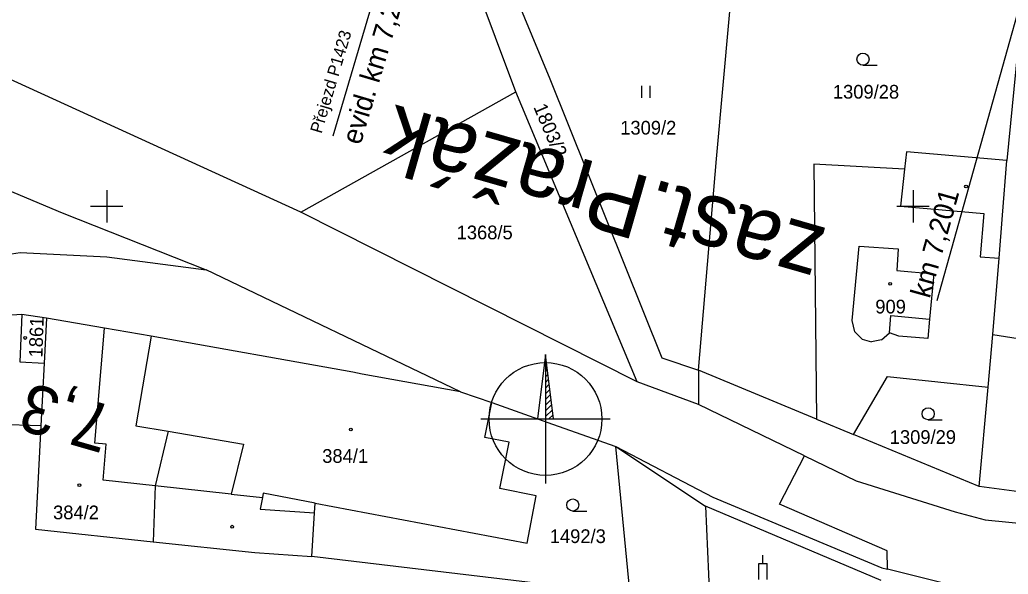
# Model space of a CAD drawing. Extents: x -779302 to -774398, y -1144902 to -1142831.
# Drawn here: x -777410.8 to -777288.2, y -1143845.6 to -1143776.9 of the extents above; entities that cross this region are included whole.
import ezdxf

# ---------------------------------------------------------------- set-up
doc = ezdxf.new("R2010")
doc.units = 0
for name, color, linetype in [('hektosit - Vrstva 5', 7, 'Continuous'), ('Hranice parcel', 7, 'Continuous'), ('Parcelní čísla', 7, 'Continuous'), ('Poz předměty', 7, 'Continuous'), ('Vnitřní kresba', 7, 'Continuous'), ('zjednodus_g_situ-seda - Vrstva 23', 7, 'Continuous'), ('zjednodus_g_situ-seda - Vrstva 4', 7, 'Continuous'), ('zjednodus_g_situ-seda - Vrstva 50', 7, 'Continuous'), ('zjednodus_g_situ-seda - Vrstva 7', 7, 'Continuous'), ('Značky budov', 7, 'Continuous'), ('Značky kultur', 7, 'Continuous')]:
    doc.layers.add(name, color=color, linetype=linetype)

msp = doc.modelspace()

# ---------------------------------------------------------------- linework, layer by layer
at = {"layer": 'hektosit - Vrstva 5'}
for p, q in [((-777400, -1143798), (-777400, -1143802)), ((-777300, -1143798), (-777300, -1143802)), ((-777402, -1143800), (-777398, -1143800)), ((-777302, -1143800), (-777298, -1143800))]:
    msp.add_line(p, q, dxfattribs=at)
at = {"layer": 'Hranice parcel'}
for p, q in [((-777286.39, -1143773.98), (-777288.38, -1143794.34)), ((-777375.94, -1143800.75), (-777349.24, -1143785.82)), ((-777334.23, -1143821.79), (-777349.24, -1143785.82)), ((-777334.23, -1143821.79), (-777375.94, -1143800.75)), ((-777356.13, -1143823.03), (-777387.68, -1143807.89)), ((-777407.46, -1143813.89), (-777410.51, -1143813.42)), ((-777407.46, -1143813.89), (-777407.75, -1143819.47)), ((-777290.68, -1143822.46), (-777290.09, -1143815.91)), ((-777290.09, -1143815.91), (-777270.07, -1143819.08)), ((-777407.75, -1143819.47), (-777408.15, -1143827.26)), ((-777311.97, -1143826.4), (-777326.6, -1143820.32)), ((-777326.6, -1143820.32), (-777326.59, -1143824.61)), ((-777326.59, -1143824.61), (-777334.23, -1143821.79)), ((-777356.13, -1143823.03), (-777352.24, -1143824.36)), ((-777291.81, -1143834.78), (-777290.68, -1143822.46)), ((-777313.47, -1143830.96), (-777326.59, -1143824.61)), ((-777408.15, -1143827.26), (-777418.55, -1143826.88)), ((-777311.97, -1143826.4), (-777307.37, -1143828.31)), ((-777291.81, -1143834.78), (-777307.37, -1143828.31)), ((-777336.84, -1143829.8), (-777325.74, -1143837.19)), ((-777335.13, -1143847.76), (-777336.84, -1143829.8)), ((-777316.56, -1143836.95), (-777313.47, -1143830.96)), ((-777286.82, -1143835.42), (-777291.81, -1143834.78)), ((-777303.21, -1143842.75), (-777316.56, -1143836.95)), ((-777303.94, -1143846.43), (-777325.74, -1143837.19)), ((-777325.74, -1143837.19), (-777324.77, -1143858.48)), ((-777303.16, -1143845.03), (-777303.21, -1143842.75))]:
    msp.add_line(p, q, dxfattribs=at)
for points in [[(-777375.94, -1143800.75), (-777415.86, -1143782.49), (-777462.27, -1143762.62), (-777556.08, -1143726.43)], [(-777349.24, -1143785.82), (-777354.31, -1143772.3), (-777358.14, -1143760.61)], [(-777354.56, -1143760.13), (-777350.41, -1143771.21), (-777345.05, -1143784.18), (-777331.15, -1143818.8), (-777326.6, -1143820.32)], [(-777326.6, -1143820.32), (-777324.39, -1143794.13), (-777321.99, -1143767.59)], [(-777437.2, -1143787.51), (-777405.54, -1143800.83), (-777387.68, -1143807.89)], [(-777288.38, -1143794.34), (-777300.82, -1143793.24), (-777301.05, -1143795.41), (-777312.29, -1143794.79), (-777311.97, -1143826.4)], [(-777290.09, -1143815.91), (-777289.33, -1143806.45), (-777288.91, -1143801.12), (-777288.38, -1143794.34)], [(-777465.49, -1143832.81), (-777457.92, -1143830.94), (-777435.72, -1143811.54), (-777423.12, -1143807.62), (-777410.71, -1143805.75), (-777400, -1143806.27), (-777387.68, -1143807.89)], [(-777410.51, -1143813.42), (-777414.33, -1143813.66), (-777426.36, -1143819.29), (-777430, -1143821.16)], [(-777410.51, -1143813.42), (-777410.76, -1143819.32), (-777407.75, -1143819.47)], [(-777394.47, -1143816.13), (-777400.29, -1143815.13), (-777407.46, -1143813.89)], [(-777394.47, -1143816.13), (-777396.39, -1143827.22), (-777392.36, -1143827.92), (-777394, -1143834.68), (-777394.22, -1143841.61)], [(-777356.13, -1143823.03), (-777368.31, -1143820.81), (-777369.47, -1143820.6), (-777394.47, -1143816.13)], [(-777307.37, -1143828.31), (-777303.15, -1143821.13), (-777290.68, -1143822.46)], [(-777374.57, -1143843.43), (-777374.21, -1143838.03), (-777374.13, -1143836.83), (-777347.87, -1143841.8), (-777346.72, -1143835.94), (-777351.23, -1143835), (-777350.1, -1143829.26), (-777353.11, -1143828.68), (-777352.24, -1143824.36)], [(-777352.24, -1143824.36), (-777344.73, -1143827.04), (-777336.84, -1143829.8)], [(-777408.15, -1143827.26), (-777408.81, -1143840.04), (-777394.22, -1143841.61)], [(-777336.84, -1143829.8), (-777324.83, -1143836.1), (-777303.85, -1143844.86), (-777303.16, -1143845.03)], [(-777313.47, -1143830.96), (-777307.07, -1143834.06), (-777294.79, -1143837.91), (-777291.06, -1143838.91), (-777215.44, -1143846.33), (-777156.34, -1143852.08), (-777155.61, -1143848.73), (-777137.5, -1143850.27)], [(-777394.22, -1143841.61), (-777381.61, -1143842.97), (-777374.57, -1143843.43)], [(-777335.13, -1143847.76), (-777340.09, -1143846.92), (-777344.36, -1143847.04), (-777374.57, -1143843.43)], [(-776998.39, -1143882.22), (-777014.02, -1143874.66), (-777035.36, -1143870.54), (-777167.58, -1143858.82), (-777281.88, -1143848.9), (-777289.53, -1143848.43), (-777292.27, -1143847.75), (-777303.16, -1143845.03)]]:
    msp.add_lwpolyline(points, dxfattribs=at)
at = {"layer": 'Poz předměty'}
for p, q in [((-777319.11, -1143844.3), (-777318.11, -1143844.3)), ((-777319.11, -1143846.3), (-777319.11, -1143844.3)), ((-777318.61, -1143844.3), (-777318.61, -1143843.3)), ((-777318.11, -1143846.3), (-777318.11, -1143844.3))]:
    msp.add_line(p, q, dxfattribs=at)
at = {"layer": 'Vnitřní kresba'}
for p, q in [((-777301.05, -1143795.41), (-777301.54, -1143800)), ((-777301.54, -1143800), (-777291.2, -1143800.92)), ((-777291.2, -1143800.92), (-777291.66, -1143806.27)), ((-777307.53, -1143814.17), (-777306.67, -1143804.95)), ((-777306.67, -1143804.95), (-777301.84, -1143805.3)), ((-777301.84, -1143805.3), (-777302.02, -1143807.96)), ((-777291.66, -1143806.27), (-777289.33, -1143806.45)), ((-777302.02, -1143807.96), (-777297.43, -1143808.38)), ((-777297.43, -1143808.38), (-777297.95, -1143813.99)), ((-777302.94, -1143815.72), (-777302.75, -1143813.55)), ((-777302.75, -1143813.55), (-777297.95, -1143813.99)), ((-777307.2, -1143815.56), (-777307.53, -1143814.17)), ((-777297.95, -1143813.99), (-777298.17, -1143816.4)), ((-777401.46, -1143829.38), (-777400.29, -1143815.13)), ((-777306.31, -1143816.47), (-777307.2, -1143815.56)), ((-777303.9, -1143816.56), (-777302.94, -1143815.72)), ((-777301.78, -1143816.1), (-777302.94, -1143815.72)), ((-777298.17, -1143816.4), (-777301.78, -1143816.1)), ((-777306.31, -1143816.47), (-777305.15, -1143816.82)), ((-777303.9, -1143816.56), (-777305.15, -1143816.82)), ((-777392.36, -1143827.92), (-777383.05, -1143829.53)), ((-777400.06, -1143829.5), (-777401.46, -1143829.38)), ((-777400.42, -1143833.97), (-777400.06, -1143829.5)), ((-777383.05, -1143829.53), (-777384.55, -1143835.72)), ((-777394, -1143834.68), (-777400.42, -1143833.97)), ((-777384.55, -1143835.72), (-777394, -1143834.68)), ((-777384.55, -1143835.72), (-777380.68, -1143836.15)), ((-777380.58, -1143835.61), (-777380.68, -1143836.15)), ((-777374.13, -1143836.83), (-777380.58, -1143835.61)), ((-777380.68, -1143836.15), (-777380.95, -1143837.57)), ((-777380.95, -1143837.57), (-777374.21, -1143838.03))]:
    msp.add_line(p, q, dxfattribs=at)
at = {"layer": 'zjednodus_g_situ-seda - Vrstva 4'}
msp.add_line((-777359.29, -1143748.5), (-777371.96, -1143791.3), dxfattribs=at)
at = {"layer": 'zjednodus_g_situ-seda - Vrstva 50'}
for p, q in [((-777345.58, -1143818.39), (-777345.58, -1143834.39)), ((-777345.58, -1143819.02), (-777345.51, -1143818.95)), ((-777345.58, -1143819.73), (-777345.43, -1143819.58)), ((-777345.58, -1143820.44), (-777345.35, -1143820.21)), ((-777345.58, -1143821.14), (-777345.27, -1143820.84)), ((-777345.58, -1143821.85), (-777345.19, -1143821.47)), ((-777345.58, -1143822.56), (-777345.11, -1143822.09)), ((-777345.58, -1143823.27), (-777345.04, -1143822.72)), ((-777345.58, -1143823.97), (-777344.96, -1143823.35)), ((-777345.58, -1143824.68), (-777344.88, -1143823.98)), ((-777345.58, -1143825.39), (-777344.8, -1143824.61)), ((-777345.58, -1143826.09), (-777344.72, -1143825.24)), ((-777345.16, -1143826.39), (-777344.64, -1143825.86)), ((-777353.58, -1143826.39), (-777337.58, -1143826.39))]:
    msp.add_line(p, q, dxfattribs=at)
for points in [[(-777345.58, -1143818.39), (-777346.58, -1143826.39)], [(-777345.58, -1143818.39), (-777345.58, -1143826.39), (-777344.58, -1143826.39), (-777345.58, -1143818.39)]]:
    msp.add_lwpolyline(points, dxfattribs=at)
msp.add_circle((-777345.58, -1143826.39), 7, dxfattribs=at)
at = {"layer": 'zjednodus_g_situ-seda - Vrstva 7'}
msp.add_line((-777286.11, -1143772.61), (-777297.03, -1143811.73), dxfattribs=at)
at = {"layer": 'Značky budov'}
for centre in [(-777293.43, -1143797.54), (-777302.83, -1143809.63), (-777410.1, -1143816.34), (-777369.73, -1143827.7), (-777403.39, -1143834.61), (-777384.44, -1143839.75)]:
    msp.add_circle(centre, 0.175, dxfattribs=at)
at = {"layer": 'Značky kultur'}
for p, q in [((-777306.21, -1143782.51), (-777304.46, -1143782.51)), ((-777333.62, -1143786.55), (-777333.62, -1143785.05)), ((-777332.62, -1143786.55), (-777332.62, -1143785.05)), ((-777298.13, -1143826.49), (-777296.38, -1143826.49)), ((-777342.2, -1143837.81), (-777340.45, -1143837.81))]:
    msp.add_line(p, q, dxfattribs=at)
for centre in [(-777306.21, -1143781.76), (-777298.13, -1143825.74), (-777342.2, -1143837.06)]:
    msp.add_circle(centre, 0.75, dxfattribs=at)

# ---------------------------------------------------------------- texts
at = {"layer": 'Parcelní čísla'}
for s, p in [('1309/28', (-777309.94, -1143786.65)), ('1309/2', (-777336.31, -1143791.11)), ('1368/5', (-777356.6, -1143804.1)), ('909', (-777304.68, -1143813.3)), ('1309/29', (-777302.89, -1143829.48)), ('384/1', (-777373.27, -1143831.83)), ('384/2', (-777406.65, -1143838.83)), ('1492/3', (-777345.05, -1143841.78))]:
    msp.add_text(s, height=1.7, dxfattribs=at).set_placement(p)
for s, rotation, p in [('1803/2', 293, (-777347.11, -1143787.69)), ('1861', 88, (-777407.97, -1143818.78))]:
    msp.add_text(s, height=1.7, rotation=rotation, dxfattribs=at).set_placement(p)
at = {"layer": 'zjednodus_g_situ-seda - Vrstva 23'}
msp.add_text('zast.Pražák', height=8, rotation=163.9829, dxfattribs=at).set_placement((-777310.5, -1143802.79))
at = {"layer": 'zjednodus_g_situ-seda - Vrstva 4'}
for s, height, p in [('evid. km 7,278', 2.5, (-777368.52, -1143792.5)), ('Přejezd P1423', 1.5, (-777373.36, -1143791.06))]:
    msp.add_text(s, height=height, rotation=73.4951, dxfattribs=at).set_placement(p)
at = {"layer": 'zjednodus_g_situ-seda - Vrstva 7'}
for s, height, rotation, p in [('km 7,201', 2.5, 74.3963, (-777297.94, -1143811.53)), ('7,3', 6, 163.9805, (-777398.9, -1143824.91))]:
    msp.add_text(s, height=height, rotation=rotation, dxfattribs=at).set_placement(p)

doc.saveas('drawing.dxf')
